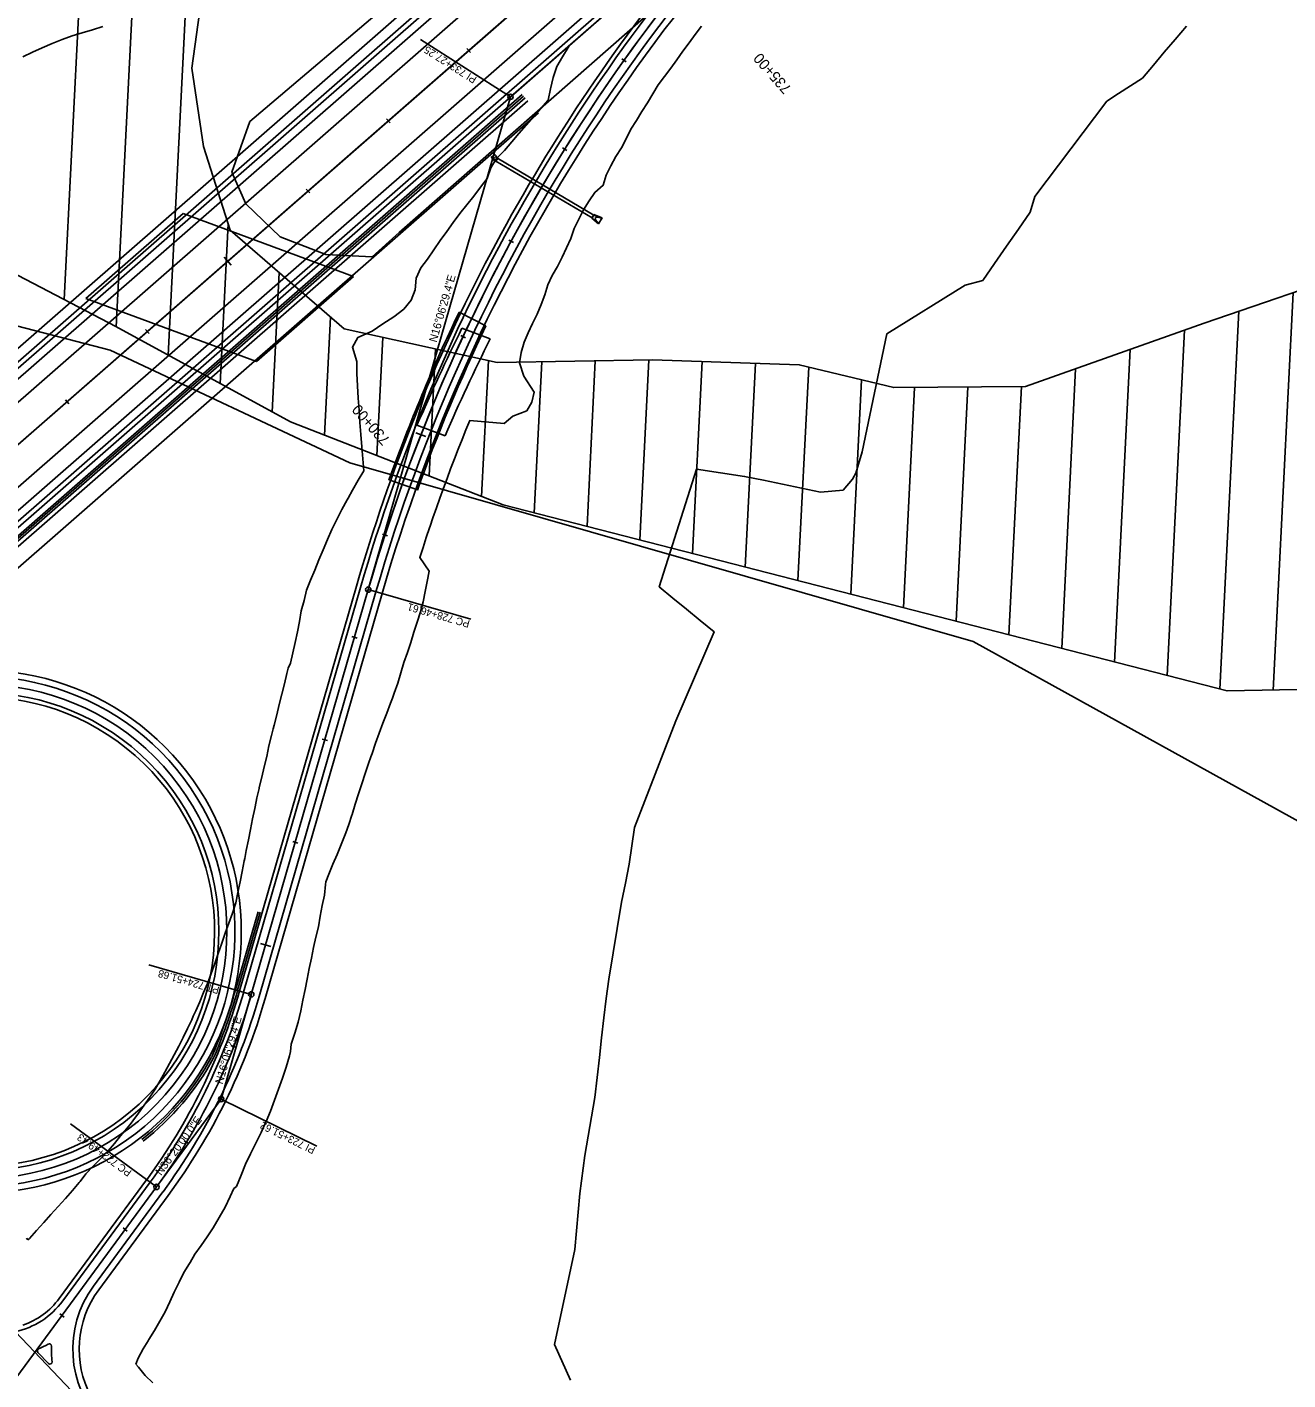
# Model space of a CAD drawing. Extents: x 1300404 to 1323571, y 234004 to 252077.
# Drawn here: x 1311251 to 1312432, y 240521 to 241789 of the extents above; entities that cross this region are included whole.
import ezdxf

# ---------------------------------------------------------------- set-up
doc = ezdxf.new("R2010")
doc.units = 0
for name, color, linetype in [('R_Bridge', 7, 'Continuous'), ('R_BRIDGE OLD', 7, 'Continuous'), ('R_Const Limits', 7, 'Continuous'), ('R_Draft', 7, 'Continuous'), ('R_Floodway', 7, 'Continuous'), ('R_Flooplain', 7, 'Continuous'), ('R_Future', 7, 'Continuous'), ('R_Horz Alg Annot', 7, 'Continuous'), ('R_Horz Alg Annot Leader', 7, 'Continuous'), ('R_Horz Alg Major Ticks', 7, 'Continuous'), ('R_Horz Alg Minor Ticks', 7, 'Continuous'), ('R_Horz Alg Station Annot', 7, 'Continuous'), ('R_Horz Alg Tangents', 7, 'Continuous'), ('R_Horz Alg Tangents Text', 7, 'Continuous'), ('R_Lane Edge', 7, 'Continuous'), ('R_Pipe Culvert', 7, 'Continuous'), ('R_Proposed', 7, 'Continuous'), ('R_Shoulder', 7, 'Continuous')]:
    doc.layers.add(name, color=color, linetype=linetype)

msp = doc.modelspace()

# ---------------------------------------------------------------- linework, layer by layer
at = {"layer": 'R_Bridge'}
for p, q in [((1311680.8, 241509.5), (1311655.7, 241522.1)), ((1311616.5, 241355.6), (1311590, 241364.9))]:
    msp.add_line(p, q, dxfattribs=at)
for radius, start, end in [(1650.1, 154.357, 160.2758), (1621.9, 154.3755, 160.2705)]:
    msp.add_arc((1313143.2, 240808), radius, start, end, dxfattribs=at)
at = {"layer": 'R_BRIDGE OLD'}
for p, q in [((1311305.8, 241535.1), (1311396.9, 241614.8)), ((1311396.9, 241614.8), (1311556.7, 241555.7)), ((1311556.7, 241555.7), (1311465.6, 241476)), ((1311305.8, 241535.1), (1311465.6, 241476)), ((1311658.3, 241507.2), (1311684.8, 241497.3)), ((1311616.1, 241416.2), (1311642.5, 241406.3))]:
    msp.add_line(p, q, dxfattribs=at)
for radius, start, end in [(1922.9, 153.6566, 156.6449), (1894.8, 153.5699, 156.603)]:
    msp.add_arc((1313381.5, 240653.9), radius, start, end, dxfattribs=at)
at = {"layer": 'R_Const Limits'}
for points in [[(1311321.6, 241789.8), (1311312.1, 241786.8), (1311302.5, 241784), (1311292.9, 241781.2), (1311283.5, 241777.8), (1311274.2, 241774), (1311265, 241770), (1311255.9, 241765.9), (1311246.8, 241761.4)], [(1311882.9, 241790.1), (1311876.9, 241782.5), (1311871.1, 241774.6), (1311865.3, 241766.7), (1311859.6, 241758.8), (1311853.9, 241750.9), (1311848.2, 241743), (1311842.3, 241735.2), (1311837.2, 241726.8), (1311832.1, 241718.5), (1311826.9, 241710.3), (1311821.8, 241701.9), (1311816.4, 241693.8), (1311812.3, 241684.8), (1311807.7, 241676.2), (1311802.5, 241668), (1311797.8, 241659.5), (1311793.5, 241650.7), (1311790.5, 241641.1), (1311782.7, 241634.5), (1311777.4, 241626.4), (1311772.3, 241618), (1311767.8, 241609.4), (1311763.4, 241600.7), (1311760.4, 241591.3), (1311756.4, 241582.4), (1311752.3, 241573.6), (1311747.7, 241565), (1311742.9, 241556.6), (1311738.7, 241547.8), (1311735.8, 241538.4), (1311732.4, 241529.3), (1311728.8, 241520.2), (1311724.5, 241511.6), (1311720.2, 241502.9), (1311716.5, 241494), (1311713.8, 241484.5), (1311712.3, 241474.6), (1311716.3, 241462.1), (1311726, 241447.2), (1311723.9, 241437.8), (1311719, 241429.6), (1311706.1, 241424.8), (1311697.7, 241418), (1311665.8, 241420.8), (1311662, 241411.8), (1311658.4, 241402.7), (1311654.8, 241393.7), (1311651.2, 241384.6), (1311647.7, 241375.4), (1311644.3, 241366.3), (1311640.9, 241357.1), (1311637.6, 241347.9), (1311634.3, 241338.7), (1311631.1, 241329.5), (1311628.5, 241321.7), (1311628, 241320.2), (1311624.9, 241311), (1311621.8, 241301.7), (1311618.8, 241292.4), (1311627.7, 241279.4), (1311625.7, 241269.9), (1311623.8, 241260.3), (1311621.8, 241250.8), (1311619.5, 241241.2), (1311616.2, 241231.7), (1311613.3, 241222.2), (1311610.3, 241212.6), (1311607.1, 241203.1), (1311603.9, 241193.7), (1311601, 241184.1), (1311598.3, 241174.5), (1311594.9, 241165), (1311593.1, 241160.3), (1311591.4, 241155.6), (1311587.8, 241146.3), (1311584, 241137), (1311580.7, 241127.5), (1311577.3, 241118.1), (1311574.1, 241108.6), (1311573, 241105.4), (1311570.8, 241099.1), (1311567.5, 241089.7), (1311564.4, 241080.2), (1311561.3, 241070.7), (1311558.3, 241061.1), (1311555.4, 241051.5), (1311555.1, 241050.8), (1311552.4, 241042), (1311549.4, 241034.1), (1311548.8, 241032.6), (1311545.1, 241023.3), (1311541.3, 241014), (1311537.4, 241004.7), (1311533.5, 240995.4), (1311530.6, 240988.4), (1311530.3, 240985.9), (1311529.5, 240975.8), (1311527.2, 240966), (1311525.4, 240956.1), (1311523.7, 240946.2), (1311521.5, 240936.4), (1311519.2, 240926.7), (1311517.3, 240916.8), (1311515.2, 240907), (1311513.1, 240897.2), (1311511.2, 240887.3), (1311509.2, 240877.5), (1311507.2, 240867.5), (1311504.8, 240856.9), (1311501.6, 240846.5), (1311498.3, 240836.2), (1311497.7, 240829.4), (1311496.6, 240825.2), (1311493.6, 240814.7), (1311490, 240804.4), (1311486.4, 240794), (1311482.7, 240783.7), (1311478.8, 240773.4), (1311474.9, 240763.8), (1311474.6, 240763.2), (1311470, 240753.2), (1311465.2, 240743.4), (1311460.2, 240733.5), (1311455.5, 240723.6), (1311451.3, 240713.3), (1311447, 240702.9), (1311444.5, 240700.8), (1311441.2, 240693.4), (1311436.3, 240683.4), (1311430.9, 240673.6), (1311425.1, 240664.1), (1311419.5, 240655.7), (1311413.8, 240647.5), (1311408.1, 240639.2), (1311403.6, 240631.6), (1311403, 240630.6), (1311397.8, 240622), (1311393.2, 240613), (1311388.7, 240603.8), (1311384.4, 240594.6), (1311380, 240585.4), (1311375.2, 240576.6), (1311370.1, 240567.9), (1311364.8, 240559.3), (1311364.1, 240558.1), (1311359.6, 240550.7), (1311354.9, 240541.8), (1311352.8, 240536.2)], [(1311760.1, 240521.2), (1311745.1, 240554.6), (1311764, 240643.6), (1311765.6, 240661.1), (1311767.1, 240678.6), (1311768.7, 240696.1), (1311773.4, 240731.8), (1311776.5, 240749.9), (1311779.7, 240768.1), (1311782.8, 240786.2), (1311785, 240804.9), (1311787.1, 240823.5), (1311789.2, 240842.1), (1311791.3, 240860.7), (1311793.5, 240879), (1311795.8, 240897.2), (1311807.7, 240969.2), (1311811.4, 240987), (1311815.1, 241004.7), (1311817.6, 241022), (1311820.1, 241039.3), (1311858.7, 241139.3), (1311894.5, 241222.6), (1311881.6, 241233.1), (1311868.8, 241243.7), (1311855.9, 241254.3), (1311843.1, 241264.8), (1311878.1, 241374.9), (1311900.6, 241371.6), (1311923.2, 241368.2), (1311940.9, 241364.6), (1311958.7, 241360.9), (1311976.5, 241357.3), (1311994.3, 241353.6), (1312015.5, 241355.4), (1312024.4, 241365.8), (1312027.4, 241371.4), (1312033.3, 241391.2), (1312056.6, 241501.9), (1312129.8, 241547.4), (1312146.3, 241551.8), (1312157.5, 241567.9), (1312168.6, 241583.9), (1312179.7, 241600), (1312190.9, 241616), (1312195.1, 241630.5), (1312262.6, 241719.8), (1312273.7, 241727), (1312284.8, 241734.2), (1312295.9, 241741.4), (1312306.2, 241753.6), (1312316.5, 241765.8), (1312326.8, 241777.9), (1312337.2, 241790.1)], [(1311251.6, 240652.7), (1311252.9, 240654.1), (1311259.6, 240661.5), (1311266.4, 240669), (1311273.1, 240676.4), (1311279.9, 240683.9), (1311286.6, 240691.4), (1311293.2, 240698.9), (1311299.7, 240706.5), (1311300.5, 240707.4), (1311305.8, 240714.5), (1311312.7, 240721.8), (1311319.8, 240729), (1311326.8, 240736.2), (1311332.6, 240743.1), (1311338.3, 240750.2), (1311344.1, 240757.2), (1311348.2, 240762.2), (1311349.8, 240764.3), (1311355.3, 240771.6), (1311360.6, 240779), (1311365.8, 240786.5), (1311370.9, 240794.1), (1311375.5, 240802), (1311379.9, 240810), (1311380.1, 240810.5), (1311384.2, 240818.1), (1311388.6, 240826.1), (1311392.9, 240834.3), (1311397, 240842.5), (1311401.1, 240850.7), (1311405, 240859.1), (1311406.5, 240862.4), (1311408.8, 240867.5), (1311412.6, 240875.9), (1311416.2, 240884.5), (1311419.7, 240893.1), (1311423.2, 240902.4), (1311426.6, 240911.8), (1311429.9, 240921.2), (1311433.2, 240930.7), (1311436.4, 240940.2), (1311439.7, 240949.6), (1311443.3, 240959), (1311446.4, 240968.5), (1311448.3, 240978.4), (1311450.3, 240988.2), (1311452.2, 240998.1), (1311454.2, 241007.9), (1311454.7, 241010.3), (1311456.1, 241017.8), (1311458.1, 241027.6), (1311460.1, 241037.4), (1311462, 241047.3), (1311464.1, 241057.1), (1311464.4, 241058.7), (1311466.2, 241066.9), (1311468.2, 241075.9), (1311468.3, 241076.7), (1311470.6, 241086.4), (1311472.9, 241096.2), (1311475.3, 241105.9), (1311477.4, 241115.7), (1311479.9, 241125.4), (1311481.5, 241131.8), (1311482.3, 241135.1), (1311484.7, 241144.8), (1311487.1, 241154.5), (1311489.6, 241164.2), (1311492.1, 241173.9), (1311494.3, 241183.7), (1311495.4, 241188.5), (1311497.5, 241193.2), (1311499.8, 241202.9), (1311502.1, 241212.6), (1311504.1, 241222.5), (1311506, 241232.3), (1311507.6, 241242.3), (1311510.5, 241251.9), (1311512.6, 241261.6), (1311516.5, 241270.9), (1311520.4, 241280.3), (1311524.2, 241290), (1311528.1, 241299.6), (1311532.2, 241309.1), (1311536.3, 241318.6), (1311541.1, 241327.9), (1311545.7, 241337.2), (1311550.7, 241346.3), (1311551.5, 241347.8), (1311555.7, 241355.5), (1311560.9, 241364.6), (1311566.4, 241373.5), (1311565.4, 241384.7), (1311564.4, 241396), (1311563.5, 241407.4), (1311562.7, 241418.8), (1311561.9, 241430.2), (1311561.1, 241441.7), (1311560.5, 241453.2), (1311559.9, 241464.7), (1311559.8, 241476.1), (1311555.7, 241489.3), (1311560.8, 241498.6), (1311574.1, 241504.3), (1311584, 241511.3), (1311594.6, 241517.9), (1311603.9, 241525.1), (1311610.6, 241533.4), (1311614.5, 241543), (1311615.4, 241554.1), (1311619.6, 241563.6), (1311626.1, 241572), (1311631.9, 241580.6), (1311637.8, 241589.3), (1311644.1, 241597.7), (1311650, 241606.3), (1311656.2, 241614.6), (1311662.8, 241622.8), (1311669.3, 241631), (1311675.7, 241639.2), (1311681.8, 241647.6), (1311685.5, 241657.4), (1311690.7, 241666.3), (1311698.1, 241673.8), (1311704.9, 241681.8), (1311711.7, 241689.6), (1311718.6, 241697.4), (1311725.3, 241705.3), (1311732.2, 241713.1), (1311739.1, 241720.8), (1311741.4, 241731.6), (1311743.9, 241742.2), (1311747.3, 241752.4), (1311752.4, 241761.4), (1311757.8, 241770.1), (1311759.2, 241772.5)], [(1311250.1, 240654.3), (1311251.6, 240652.7)], [(1311352.8, 240536.2), (1311355.1, 240533.3), (1311361.5, 240525.7), (1311368.6, 240518.6)]]:
    msp.add_lwpolyline(points, dxfattribs=at)
at = {"layer": 'R_Draft'}
for p, q in [((1308397, 238971.9), (1312368.4, 242444.5)), ((1308407.8, 238959.5), (1312379.2, 242432.1)), ((1308447.3, 238914.3), (1312418.7, 242386.9)), ((1308458.2, 238901.9), (1312429.6, 242374.5)), ((1309037.8, 239548.2), (1312137.6, 242258.7)), ((1309184.5, 239689.1), (1312131.4, 242265.9)), ((1309193.7, 239678.5), (1312140.6, 242255.3)), ((1309413.9, 239721.6), (1312065.7, 242040.4)), ((1309410.9, 239725), (1311988, 241978.4)), ((1309410.9, 239725), (1311988, 241978.4))]:
    msp.add_line(p, q, dxfattribs=at)
at = {"layer": 'R_Floodway'}
for p, q in [((1311285.5, 241534), (1311311.2, 242047.1)), ((1311334.3, 241508.5), (1311359.7, 242015.5)), ((1311383, 241481.9), (1311407.2, 241965.9)), ((1311431.7, 241455.4), (1311439.2, 241605)), ((1311480.5, 241428.8), (1311487, 241559.2)), ((1312418.6, 241168), (1312437.2, 241540.4)), ((1312368.6, 241168.9), (1312386.3, 241523)), ((1311529.4, 241407), (1311535, 241517.6)), ((1311578.5, 241387.9), (1311584.1, 241498.5)), ((1312319.1, 241181.6), (1312335.4, 241505.3)), ((1311627.6, 241368.7), (1311633.6, 241487.7)), ((1312269.7, 241194.3), (1312284.4, 241487.2)), ((1311676.7, 241349.5), (1311683.1, 241476.8)), ((1311726, 241334.2), (1311733.1, 241475.7)), ((1311775.5, 241321.5), (1311783.2, 241476.5)), ((1311824.9, 241308.8), (1311833.3, 241477.3)), ((1311874.3, 241296), (1311883.3, 241475.9)), ((1311923.7, 241283.3), (1311933.3, 241474.2)), ((1311973.2, 241270.6), (1311983.2, 241470.7)), ((1312022.6, 241257.9), (1312032.6, 241458.8)), ((1312220.3, 241207), (1312233.4, 241469.2)), ((1312072, 241245.2), (1312082.4, 241451.6)), ((1312121.4, 241232.5), (1312132.4, 241452.1)), ((1312170.9, 241219.8), (1312182.5, 241452.5))]:
    msp.add_line(p, q, dxfattribs=at)
for points in [[(1312719.3, 241174), (1312375.3, 241167.2), (1311696.9, 241341.7), (1311497.5, 241419.5), (1311333.8, 241508.8), (1311059.1, 241652.1), (1310740.8, 241795.1), (1310453.3, 241924.5), (1310367.2, 241994.2), (1310267.8, 242111.7), (1309996.2, 242391.6), (1309869.7, 242546.7), (1309624.5, 242919.6)], [(1311431.5, 241940.6), (1311405.2, 241750.8), (1311416, 241677.6), (1311441.1, 241598.9), (1311547.8, 241506.5), (1311691.4, 241475), (1311836.7, 241477.4), (1311974.4, 241472.9), (1312062.9, 241451.5), (1312186.3, 241452.5), (1312353.8, 241511.8), (1312501.5, 241562.5)]]:
    msp.add_lwpolyline(points, dxfattribs=at)
at = {"layer": 'R_Flooplain'}
for p, q in [((1311459.5, 241700.8), (1312470.1, 242559.7)), ((1312629.3, 242500.9), (1311599.5, 241597)), ((1311442.6, 241653.3), (1311459.5, 241700.8)), ((1311455.7, 241623.6), (1311442.6, 241653.3)), ((1311488, 241592.9), (1311455.7, 241623.6)), ((1311530.7, 241576.3), (1311488, 241592.9)), ((1311599.5, 241597), (1311574.2, 241574.1)), ((1311574.2, 241574.1), (1311530.7, 241576.3))]:
    msp.add_line(p, q, dxfattribs=at)
msp.add_lwpolyline([(1308850.4, 242983.4), (1308921.9, 242863.7), (1309009.8, 242685), (1309044.1, 242596.2), (1309055.9, 242542.4), (1309352.1, 242367.8), (1309503.2, 242292.4), (1309669.5, 242230.8), (1309815.5, 242150.9), (1309936.7, 242057.6), (1310419.4, 241839.8), (1310733.2, 241727.2), (1311043.7, 241597.8), (1311103.2, 241577.9), (1311152.8, 241553.6), (1311178, 241525.7), (1311328.5, 241486.7), (1311553.1, 241381), (1311870.3, 241290), (1312137.5, 241213.6), (1312460.1, 241035.3)], dxfattribs=at)
at = {"layer": 'R_Future'}
for p, q in [((1311714.8, 241726.2), (1309950.4, 240183.5)), ((1311716.1, 241724.7), (1309951.7, 240182)), ((1311717.4, 241723.2), (1309953.1, 240180.5)), ((1311720, 241720.2), (1309955.7, 240177.5)), ((1311729.9, 241708.9), (1311093.2, 241152.2)), ((1311446, 240887.1), (1311467.2, 240960.3)), ((1311448, 240886.6), (1311469.2, 240960))]:
    msp.add_line(p, q, dxfattribs=at)
for centre, radius, start, end in [((1311206.5, 240941.7), 239, 234.164, 118.3011), ((1311206.5, 240941.7), 245, 246.6809, 113.1599), ((1311206.5, 240941.7), 231.5, 223.6667, 131.1667), ((1311206.5, 240941.7), 231.5, 223.6667, 131.1667), ((1311206.5, 240941.7), 231.5, 223.6667, 131.1667), ((1311206.5, 240941.7), 231.5, 223.6667, 131.1667), ((1311206.5, 240941.7), 220, 236.5053, 138.8983), ((1311206.5, 240941.7), 224, 223.6667, 131.1667), ((1310910.5, 241041.8), 557.5, 337.0176, 343.8918), ((1310910.5, 241041.8), 559.5, 337.0079, 343.8918), ((1311206.5, 240941.7), 247, 307.9336, 331.5655), ((1311206.5, 240941.7), 249, 307.9336, 331.5874)]:
    msp.add_arc(centre, radius, start, end, dxfattribs=at)
at = {"layer": 'R_Horz Alg Annot Leader'}
for points in [[(1311703.8, 241724), (1311619.5, 241777.7)], [(1311570.5, 241262.2), (1311666.6, 241234.5)], [(1311460.9, 240882.8), (1311364.8, 240910.5)], [(1311432.6, 240784.6), (1311522.3, 240740.4)], [(1311372, 240702.3), (1311291.5, 240761.6)]]:
    msp.add_lwpolyline(points, dxfattribs=at)
at = {"layer": 'R_Horz Alg Major Ticks'}
for points in [[(1311435.5, 241573.7), (1311442.1, 241566.2)], [(1311615.2, 241409.2), (1311624.5, 241405.6)], [(1311469.5, 240930.6), (1311479.1, 240927.8)]]:
    msp.add_lwpolyline(points, dxfattribs=at)
at = {"layer": 'R_Horz Alg Minor Ticks'}
for points in [[(1311663, 241769.3), (1311666.2, 241765.5)], [(1311808.1, 241759.6), (1311812.2, 241756.7)], [(1311587.7, 241703.4), (1311591, 241699.7)], [(1311752.5, 241676.3), (1311756.7, 241673.6)], [(1311512.4, 241637.6), (1311515.7, 241633.9)], [(1311702.1, 241589.8), (1311706.5, 241587.4)], [(1311361.8, 241506), (1311365.1, 241502.2)], [(1311657.1, 241500.3), (1311661.6, 241498.2)], [(1311286.6, 241440.1), (1311289.8, 241436.4)], [(1311583.8, 241314), (1311588.5, 241312.5)], [(1311555.2, 241218.1), (1311560, 241216.8)], [(1311527.4, 241122.1), (1311532.2, 241120.7)], [(1311499.7, 241026), (1311504.5, 241024.6)], [(1311442, 240834.8), (1311446.7, 240833)], [(1311398, 240745.6), (1311402.3, 240743)], [(1311340.7, 240664), (1311344.7, 240661)], [(1311281.5, 240583.4), (1311285.5, 240580.4)]]:
    msp.add_lwpolyline(points, dxfattribs=at)
at = {"layer": 'R_Horz Alg Tangents'}
for p, q in [((1311703.8, 241724), (1312065.7, 242040.4)), ((1311570.5, 241262.2), (1311703.8, 241724)), ((1311432.6, 240784.6), (1311460.9, 240882.8)), ((1311372, 240702.3), (1311432.6, 240784.6))]:
    msp.add_line(p, q, dxfattribs=at)
at = {"layer": 'R_Lane Edge'}
for p, q in [((1311453.7, 240884.9), (1311563.3, 241264.3)), ((1311468.1, 240880.7), (1311577.7, 241260.1)), ((1311284.2, 240595.5), (1311366, 240706.7)), ((1311313, 240609.4), (1311378.1, 240697.9)), ((1311260.8, 240547.3), (1311270.7, 240537))]:
    msp.add_line(p, q, dxfattribs=at)
for centre, radius, start, end in [((1313143.2, 240808), 1629.5, 131.1667, 163.8918), ((1313143.2, 240808), 1644.5, 136.4518, 163.8918), ((1310910.5, 241041.8), 565.5, 323.6667, 343.8918), ((1310910.5, 241041.8), 580.5, 323.6667, 343.8918), ((1311393.6, 240550.2), 100, 143.6667, 223.6667), ((1311223.7, 240639.9), 75, 282.2398, 323.6667), ((1311262.3, 240548.7), 2, 112.8975, 223.6667), ((1311223.7, 240639.9), 97, 292.8975, 298.9273), ((1311271.6, 240553.3), 2, 358.544, 118.9279), ((1311393.6, 240550.2), 120, 178.544, 185.562), ((1311272.2, 240538.3), 2, 223.6667, 5.562)]:
    msp.add_arc(centre, radius, start, end, dxfattribs=at)
at = {"layer": 'R_Pipe Culvert'}
for p, q in [((1311690.1, 241663.8), (1311780.4, 241610.5)), ((1311692.5, 241665.9), (1311781.9, 241613.1)), ((1311781.9, 241613.6), (1311780, 241610.4)), ((1311780.4, 241610.5), (1311780, 241610.4)), ((1311782, 241613.2), (1311780.4, 241610.5)), ((1311780.4, 241610.5), (1311786.4, 241605.3)), ((1311781.9, 241613.6), (1311789.6, 241610.7)), ((1311782, 241613.2), (1311781.9, 241613.6)), ((1311782, 241613.2), (1311789.5, 241610.4)), ((1311785.1, 241611.3), (1311789.6, 241610.7)), ((1311789.5, 241610.4), (1311785.1, 241611.3)), ((1311789.6, 241610.7), (1311786.3, 241605)), ((1311780, 241610.4), (1311786.3, 241605)), ((1311783.5, 241608.7), (1311786.3, 241605)), ((1311786.4, 241605.3), (1311783.5, 241608.7))]:
    msp.add_line(p, q, dxfattribs=at)
for points in [[(1311692.6, 241666.1), (1311689.4, 241663.2), (1311685.8, 241667.1), (1311689, 241670)], [(1311691.7, 241666.1), (1311689.4, 241664.1), (1311687.7, 241666), (1311689.9, 241668)]]:
    msp.add_lwpolyline(points, close=True, dxfattribs=at)
msp.add_arc((1311784.9, 241609.7), 1.66, 82.4536, 216.409, dxfattribs=at)
at = {"layer": 'R_Proposed'}
for p, q in [((1308463.1, 238968), (1312793.8, 242754.8)), ((1308427.6, 238936.9), (1312399, 242409.5)), ((1309180.4, 239595.2), (1312399, 242409.5)), ((1309180.4, 239595.2), (1312399, 242409.5)), ((1309180.4, 239595.2), (1312051.5, 242105.7)), ((1311460.9, 240882.8), (1311570.5, 241262.2)), ((1311460.9, 240882.8), (1311570.5, 241262.2)), ((1310682.6, 241150.3), (1311414.9, 240383)), ((1311241.2, 240524.4), (1311372, 240702.3)), ((1311241.2, 240524.4), (1311372, 240702.3)), ((1311241.2, 240524.4), (1311372, 240702.3))]:
    msp.add_line(p, q, dxfattribs=at)
for centre in [(1311703.8, 241724), (1311570.5, 241262.2), (1311460.9, 240882.8), (1311432.6, 240784.6), (1311372, 240702.3)]:
    msp.add_circle(centre, 2.5, dxfattribs=at)
for centre, radius, start, end in [((1313143.2, 240808), 1637, 131.1667, 163.8918), ((1313143.2, 240808), 1637, 131.1667, 163.8918), ((1313143.2, 240808), 1637, 131.1667, 163.0419), ((1310910.5, 241041.8), 573, 323.6667, 343.8918), ((1310910.5, 241041.8), 573, 323.6667, 343.8918)]:
    msp.add_arc(centre, radius, start, end, dxfattribs=at)
at = {"layer": 'R_Shoulder'}
for p, q in [((1311449.9, 240886), (1311559.4, 241265.4)), ((1311473.9, 240879.1), (1311583.5, 241258.5)), ((1311280.9, 240597.9), (1311362.8, 240709.1)), ((1311317.9, 240605.9), (1311382.9, 240694.3))]:
    msp.add_line(p, q, dxfattribs=at)
for centre, radius, start, end in [((1313143.2, 240808), 1623.5, 131.1667, 163.8918), ((1313143.2, 240808), 1648.5, 140.4948, 163.8918), ((1310910.5, 241041.8), 561.5, 323.6667, 343.8918), ((1310910.5, 241041.8), 586.5, 323.6667, 343.8918), ((1311223.7, 240639.9), 71, 289.0225, 323.6667), ((1311393.6, 240550.2), 94, 143.6667, 207.9824)]:
    msp.add_arc(centre, radius, start, end, dxfattribs=at)

# ---------------------------------------------------------------- texts
at = {"layer": 'R_Horz Alg Annot'}
for s, rotation, p in [('PI 733+27.25', 147.5292, (1311672.8, 241742)), ('PC 728+46.61', 163.8918, (1311666.2, 241233)), ('PT 724+51.68', 163.8918, (1311431.5, 240889.7)), ('PI 723+51.62', 153.7792, (1311521.6, 240739.1)), ('PC 722+49.43', 143.6667, (1311349.4, 240717.1))]:
    msp.add_text(s, height=7, rotation=rotation, dxfattribs=at).set_placement(p)
at = {"layer": 'R_Horz Alg Station Annot'}
for s, p in [('735+00', (1311967.7, 241732.2)), ('730+00', (1311591.5, 241402.9))]:
    msp.add_text(s, height=10, rotation=131.1667, dxfattribs=at).set_placement(p)
at = {"layer": 'R_Horz Alg Tangents Text'}
for s, rotation, p in [('N16%%d06\'29.4"E', 73.8918, (1311634.4, 241493.4)), ('N16%%d06\'29.4"E', 73.8918, (1311433.9, 240798.1)), ('N36%%d20\'00.0"E', 53.6667, (1311376.4, 240712.5))]:
    msp.add_text(s, height=7.5, rotation=rotation, dxfattribs=at).set_placement(p)

doc.saveas('drawing.dxf')
